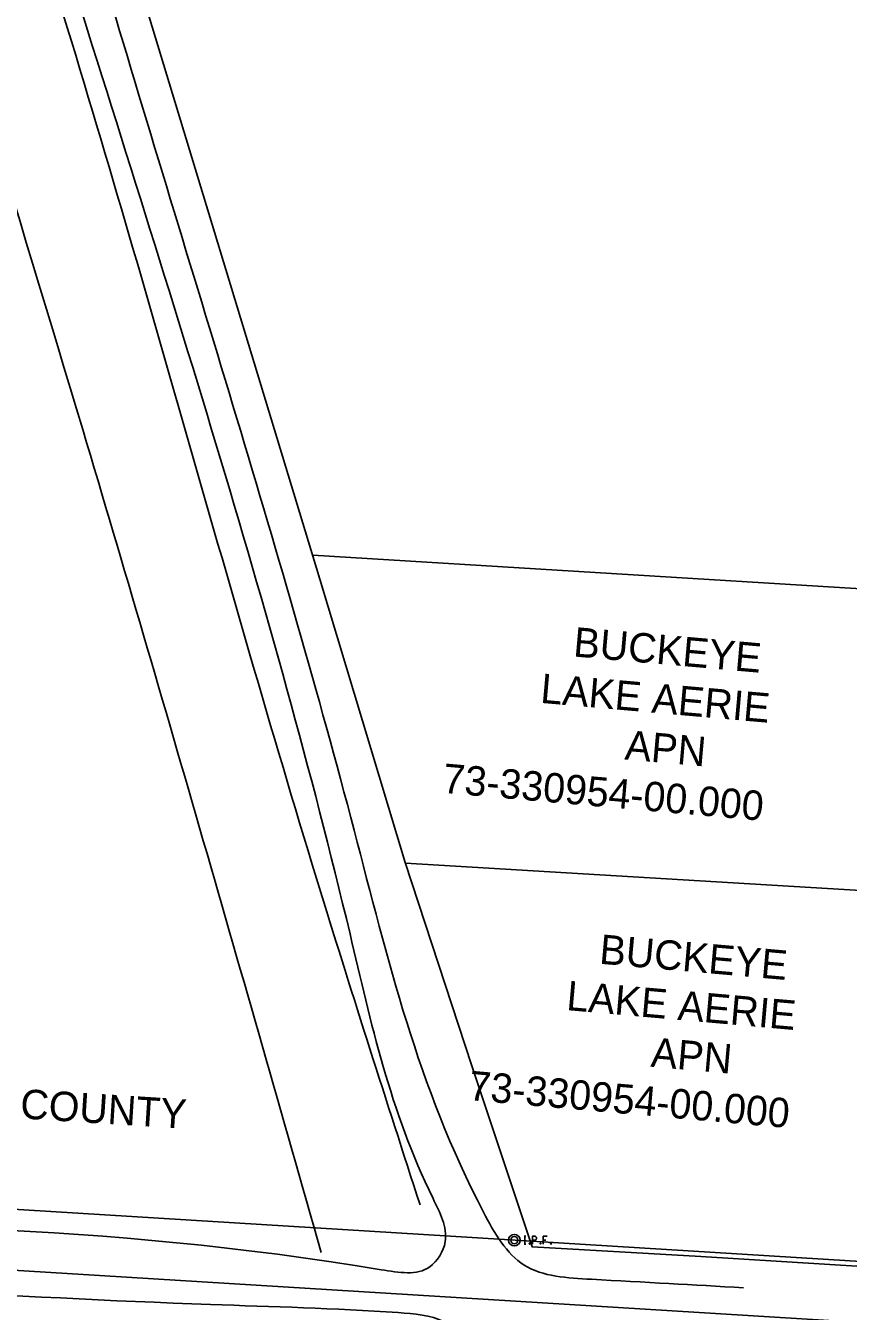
# Model space of a CAD drawing. Extents: x 1957117 to 1971063, y 701601 to 715861.
# Drawn here: x 1963031 to 1963478, y 701962 to 702661 of the extents above; entities that cross this region are included whole.
import ezdxf

# ---------------------------------------------------------------- set-up
doc = ezdxf.new("R2010")
doc.units = 0
for name, color, linetype in [('DV_X_County_Line', 7, 'Continuous'), ('DV_X_Property_Line', 7, 'Continuous'), ('GE_P_CL_50', 7, 'Continuous'), ('HY_X_Water_Edge', 7, 'Continuous'), ('PV_P_Shoulder', 7, 'Continuous'), ('RS_Raster1', 7, 'Continuous'), ('RW_X_Fee_RW', 7, 'Continuous'), ('SC_Scratch1', 7, 'Continuous'), ('SC_Shading3', 7, 'Continuous'), ('SC_Shading5', 7, 'Continuous'), ('SH_Text', 7, 'Continuous'), ('SV_X_Text', 7, 'Continuous')]:
    doc.layers.add(name, color=color, linetype=linetype)

msp = doc.modelspace()

# ---------------------------------------------------------------- linework, layer by layer
at = {"layer": 'DV_X_County_Line'}
msp.add_line((1957993.26, 702294.22), (1968721.74, 701633.51), dxfattribs=at)
at = {"layer": 'DV_X_Property_Line'}
for p, q in [((1963551.37, 702350.49), (1963187.07, 702372.92)), ((1963237.45, 702205.5), (1963541.32, 702187.26))]:
    msp.add_line(p, q, dxfattribs=at)
at = {"layer": 'GE_P_CL_50'}
msp.add_circle((1963296.66, 702000.69), 1.94, dxfattribs=at)
at = {"layer": 'HY_X_Water_Edge'}
msp.add_spline([(1963191.72, 701994.05), (1963062.05, 702441.17), (1962863.49, 703169.36), (1962827.53, 703438.69), (1962823.21, 703537.41), (1962817.96, 703593.87), (1962817.97, 703697.32), (1962828.58, 703804.23), (1962836.46, 703844.73), (1962850.69, 703896), (1962867.25, 703938.85), (1962873.85, 703992.35), (1962884.14, 704091.37), (1962891.24, 704140.85), (1962897.38, 704180.53), (1962905.47, 704230.98), (1962943.95, 704328.02), (1962948.54, 704378.84), (1962964.11, 704426.26), (1963004.89, 704570.73), (1963042.05, 704716.52), (1963062.04, 704814.42), (1963072.17, 704860.24), (1963090.02, 704956.8), (1963107.07, 705031.78), (1963133.77, 705105.74), (1963148.69, 705206.74), (1963175.48, 705301.06), (1963191.64, 705353.42), (1963210.99, 705447.29), (1963219.53, 705497.27), (1963230.12, 705549.47), (1963251.05, 705591.16), (1963275.29, 705693.43), (1963292.98, 705784.03), (1963302.84, 705839.65), (1963335.13, 705936.77), (1963359.75, 706046.75), (1963389.13, 706177.3), (1963417.83, 706273.46), (1963475.87, 706451.9), (1963533.78, 706640.53), (1963553.86, 706696.98), (1963580.18, 706715.43), (1963609.17, 706718.73), (1963617.06, 706714.69), (1963619.45, 706694.68), (1963564.28, 706533.07), (1963531.85, 706395.23), (1963434.4, 706006.96), (1963354.09, 705679.19), (1963237.51, 705206.07), (1963167.37, 704892.96), (1963059.15, 704434.18), (1962907.91, 703908.74), (1962877.46, 703703.33), (1962898.36, 703412.12), (1962942.65, 703052.27), (1963048.96, 702674.87), (1963191.47, 702189.67), (1963245.4, 702019.83)], degree=3, dxfattribs=at)
at = {"layer": 'RW_X_Fee_RW'}
msp.add_line((1957995.29, 702327.16), (1968723.77, 701666.44), dxfattribs=at)
msp.add_lwpolyline([(1963555.85, 701982.02), (1963398.07, 701991.87), (1963306.37, 701997.04), (1963273.63, 702095.5), (1963237.32, 702205.89), (1963191.02, 702359.9), (1963032.12, 702883.37)], dxfattribs=at)
at = {"layer": 'SC_Shading3'}
for points in [[(1963301.95, 702002.79), (1963302.87, 702002.79)], [(1963301.95, 701998.59), (1963302.87, 701998.59)], [(1963302.41, 701998.59), (1963302.41, 702002.79)], [(1963304.93, 701999.16), (1963305.07, 701999.16), (1963305.16, 701999.09), (1963305.25, 701998.96), (1963305.25, 701998.79), (1963305.16, 701998.66), (1963305.07, 701998.59), (1963304.93, 701998.59), (1963304.84, 701998.66), (1963304.75, 701998.79), (1963304.75, 701998.96), (1963304.84, 701999.09), (1963304.93, 701999.16)], [(1963306.52, 701998.59), (1963306.52, 702002.79), (1963307.91, 702002.79), (1963308.05, 702002.76), (1963308.25, 702002.69), (1963308.34, 702002.63), (1963308.43, 702002.56), (1963308.54, 702002.4), (1963308.63, 702002.23), (1963308.69, 702001.97), (1963308.69, 702001.57), (1963308.66, 702001.44), (1963308.6, 702001.24), (1963308.49, 702001.01), (1963308.37, 702000.91), (1963308.28, 702000.84), (1963308.14, 702000.78), (1963307.91, 702000.74), (1963306.52, 702000.74)], [(1963310.83, 701999.16), (1963310.97, 701999.16), (1963311.06, 701999.09), (1963311.15, 701998.96), (1963311.15, 701998.79), (1963311.06, 701998.66), (1963310.97, 701998.59), (1963310.83, 701998.59), (1963310.74, 701998.66), (1963310.66, 701998.79), (1963310.66, 701998.96), (1963310.74, 701999.09), (1963310.83, 701999.16)], [(1963314.42, 702002.79), (1963312.42, 702002.79), (1963312.42, 701998.59)], [(1963312.42, 702000.74), (1963313.84, 702000.74)], [(1963316.47, 701999.16), (1963316.62, 701999.16), (1963316.7, 701999.09), (1963316.79, 701998.96), (1963316.79, 701998.79), (1963316.7, 701998.66), (1963316.62, 701998.59), (1963316.47, 701998.59), (1963316.39, 701998.66), (1963316.3, 701998.79), (1963316.3, 701998.96), (1963316.39, 701999.09), (1963316.47, 701999.16)]]:
    msp.add_lwpolyline(points, dxfattribs=at)
msp.add_circle((1963296.66, 702000.69), 3.15, dxfattribs=at)
at = {"layer": 'SC_Shading5'}
for points in [[(1962926.26, 703242.19), (1962946.25, 703107.39), (1962986.25, 702923.11), (1963051.63, 702699.79), (1963207.34, 702167.12), (1963252.46, 702023.36), (1963259.06, 701999.86), (1963250.68, 701986.22), (1963224.36, 701984.64), (1962805.91, 702009.44)], [(1963421.17, 701974.83), (1963338.55, 701979.45), (1963302.07, 701987.11), (1963279.87, 702015.93), (1963209.59, 702223.42), (1963077.93, 702671.95), (1963000.54, 702945.2), (1962972.61, 703059.9), (1962957.21, 703157.66), (1962944.96, 703244.11)], [(1962803.27, 701984.67), (1963131.49, 701965.75), (1963233.59, 701961.34), (1963258.54, 701956.38), (1963275.42, 701941.14), (1963285.27, 701923.87), (1963305.17, 701865.89)]]:
    msp.add_spline(points, degree=3, dxfattribs=at)

# ---------------------------------------------------------------- texts
at = {"layer": 'PV_P_Shoulder'}
msp.add_text('887.06', height=0.35, dxfattribs=at).set_placement((1963294.97, 702000.34))
at = {"layer": 'RS_Raster1'}
msp.add_text('2', height=0.35, dxfattribs=at).set_placement((1963296.47, 702000.69))
at = {"layer": 'SC_Scratch1'}
msp.add_text('IPIN', height=0.35, dxfattribs=at).set_placement((1963296.66, 702000.34))
at = {"layer": 'SH_Text'}
msp.add_text('LICKING COUNTY ', height=16, rotation=356.35451, dxfattribs=at).set_placement((1962936.42, 702072.73))
at = {"layer": 'SV_X_Text'}
for s, p in [('BUCKEYE ', (1963328.35, 702317.92)), ('LAKE AERIE', (1963310.46, 702292.71)), ('APN ', (1963356.33, 702261.93)), ('73-330954-00.000', (1963257.24, 702243.83)), ('BUCKEYE ', (1963342.49, 702150.96)), ('LAKE AERIE', (1963324.6, 702125.75)), ('APN ', (1963370.48, 702094.97)), ('73-330954-00.000', (1963271.38, 702076.87))]:
    msp.add_text(s, height=16, rotation=355, dxfattribs=at).set_placement(p)

doc.saveas('drawing.dxf')
